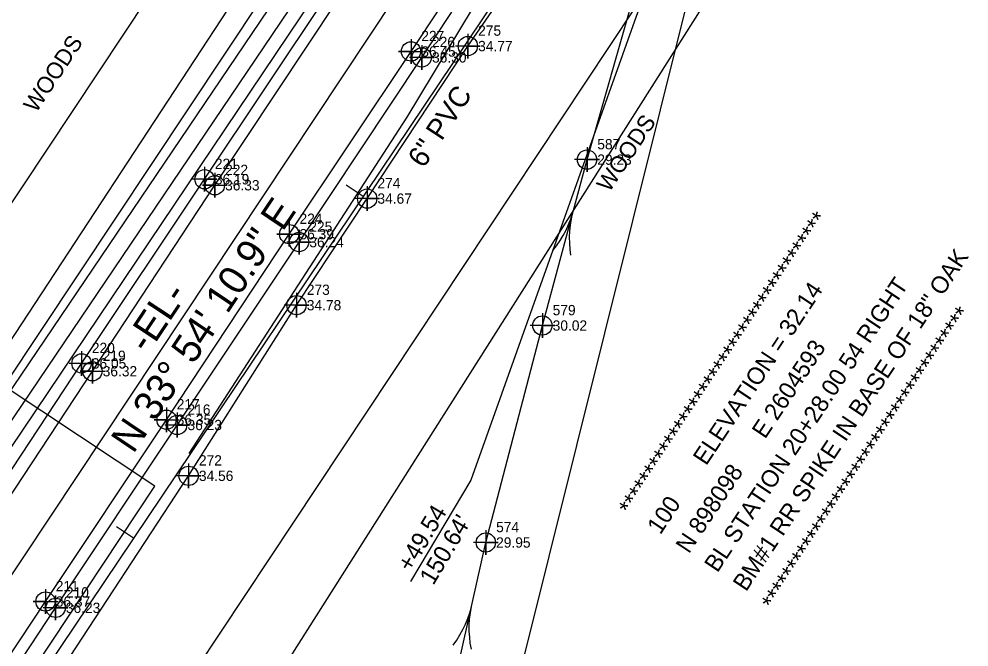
# Model space of a CAD drawing. Extents: x 2603627 to 2605187, y 896619 to 899063.
# Drawn here: x 2604393.2 to 2604624, y 897913.7 to 898066.2 of the extents above; entities that cross this region are included whole.
import ezdxf

# ---------------------------------------------------------------- set-up
doc = ezdxf.new("R2010")
doc.units = 0
for name, color, linetype in [('CTL Sheet Text', 7, 'Continuous'), ('Exist DTM Drainline Cogo Elevation', 7, 'Continuous'), ('Exist DTM Drainline Cogo Number', 7, 'Continuous'), ('Exist DTM Drainline Cogo Point CELL', 7, 'Continuous'), ('Exist Guardrail', 7, 'Continuous'), ('Exist Horizontal Alignment', 7, 'Continuous'), ('Exist Horizontal Alignment Direction Label', 7, 'Continuous'), ('Exist Horizontal Baseline Alignment', 7, 'Continuous'), ('Exist Horizontal Baseline Alignment Direction Label', 7, 'Continuous'), ('Exist Horizontal Baseline Alignment Tick small', 7, 'Continuous'), ('Exist Hydro Stream Flow Arrow CELL', 7, 'Continuous'), ('Exist Hydro Stream or Body of Water', 7, 'Continuous'), ('Exist Property Line', 7, 'Continuous'), ('Exist Property Tie Line Leader', 7, 'Continuous'), ('Exist Property Tie Line Text', 7, 'Continuous'), ('Exist Right of Way Line', 7, 'Continuous'), ('Exist Roads EOP', 7, 'Continuous'), ('Exist Roads EOP Cogo Elevation', 7, 'Continuous'), ('Exist Roads EOP Cogo Number', 7, 'Continuous'), ('Exist Roads EOP Cogo Point CELL', 7, 'Continuous'), ('Exist Roads EOT', 7, 'Continuous'), ('Exist Roads EOT Cogo Elevation', 7, 'Continuous'), ('Exist Roads EOT Cogo Number', 7, 'Continuous'), ('Exist Roads EOT Cogo Point CELL', 7, 'Continuous'), ('Exist Utilities Telephone UG Cable SUE LOS C', 7, 'Continuous'), ('Exist Utilities Telephone UG FO SUE LOS C', 7, 'Continuous'), ('Exist Utilities Water UG Line SUE LOS B', 7, 'Continuous'), ('Exist Utilities Water UG Line SUE LOS B Cogo Elevation', 7, 'Continuous'), ('Exist Utilities Water UG Line SUE LOS B Cogo Number', 7, 'Continuous'), ('Exist Utilities Water UG Line SUE LOS B Cogo Point CELL', 7, 'Continuous'), ('Exist Utilities Water UG Line SUE LOS B Text', 7, 'Continuous'), ('Exist Vegetation Woods Line', 7, 'Continuous'), ('Exist Vegetation Woods Line Text', 7, 'Continuous')]:
    doc.layers.add(name, color=color, linetype=linetype)

# ---------------------------------------------------------------- blocks, each defined once
blk = doc.blocks.new('EXIST ROADS EOP COGO POINT')
at = {"layer": 'Exist Roads EOP Cogo Point CELL'}
blk.add_lwpolyline([(0, 0.06), (0, -0.06), (0, 0), (0.06, 0), (-0.06, 0)], dxfattribs=at)
blk.add_circle((0, 0), 0.0469, dxfattribs=at)
blk = doc.blocks.new('EXIST ROADS EOT COGO POINT')
at = {"layer": 'Exist Roads EOT Cogo Point CELL'}
blk.add_lwpolyline([(0, 0.06), (0, -0.06), (0, 0), (-0.06, 0), (0.06, 0)], dxfattribs=at)
blk.add_circle((0, 0), 0.0469, dxfattribs=at)
blk = doc.blocks.new('EXIST UTILITIES WATER UG LINE SUE LOS B COGO POINT')
at = {"layer": 'Exist Utilities Water UG Line SUE LOS B Cogo Point CELL'}
blk.add_lwpolyline([(0, 0.06), (0, -0.06), (0, 0), (0.06, 0), (-0.06, 0)], dxfattribs=at)
blk.add_circle((0, 0), 0.0469, dxfattribs=at)
blk = doc.blocks.new('EXIST DTM DRAINLINE COGO POINT')
at = {"layer": 'Exist DTM Drainline Cogo Point CELL'}
blk.add_lwpolyline([(0, 0.06), (0, -0.06), (0, 0), (0.06, 0), (-0.06, 0)], dxfattribs=at)
blk.add_circle((0, 0), 0.0469, dxfattribs=at)

msp = doc.modelspace()

# ---------------------------------------------------------------- linework, layer by layer
at = {"layer": 'Exist Guardrail'}
msp.add_lwpolyline([(2604516.08, 898089.95), (2604487.4, 898042.34), (2604434.45, 897960.66)], dxfattribs=at)
at = {"layer": 'Exist Horizontal Alignment'}
msp.add_line((2604046.33, 897411.6), (2604501.12, 898096.36), dxfattribs=at)
at = {"layer": 'Exist Horizontal Baseline Alignment'}
msp.add_line((2604301.74, 897762.53), (2604544.96, 898124.44), dxfattribs=at)
at = {"layer": 'Exist Horizontal Baseline Alignment Tick small'}
for p, q in [((2604476.83, 898023.06), (2604472.68, 898025.85)), ((2604421.06, 897940.07), (2604416.91, 897942.85))]:
    msp.add_line(p, q, dxfattribs=at)
at = {"layer": 'Exist Hydro Stream Flow Arrow CELL'}
for p, q in [((2604526.4, 898014.23), (2604526.4, 898014.23)), ((2604502.01, 897918.51), (2604502.01, 897918.51))]:
    msp.add_line(p, q, dxfattribs=at)
for points in [[(2604522.9, 898009.99), (2604523.82, 898011.13), (2604524.64, 898012.39), (2604525.43, 898013.64), (2604526.1, 898014.92), (2604526.71, 898016.27), (2604527.25, 898017.66), (2604527.7, 898019.06)], [(2604527.31, 898008.81), (2604527.08, 898010.25), (2604527.01, 898011.75), (2604526.95, 898013.23), (2604527.02, 898014.67), (2604527.17, 898016.15), (2604527.4, 898017.62), (2604527.7, 898019.06)], [(2604498.68, 897914.14), (2604499.56, 897915.31), (2604500.32, 897916.6), (2604501.06, 897917.88), (2604501.68, 897919.19), (2604502.23, 897920.57), (2604502.71, 897921.98), (2604503.11, 897923.39)], [(2604503.15, 897913.13), (2604502.85, 897914.57), (2604502.72, 897916.06), (2604502.6, 897917.54), (2604502.6, 897918.98), (2604502.69, 897920.46), (2604502.86, 897921.95), (2604503.11, 897923.39)]]:
    msp.add_lwpolyline(points, dxfattribs=at)
at = {"layer": 'Exist Hydro Stream or Body of Water'}
msp.add_lwpolyline([(2604496.63, 897894.57), (2604506.62, 897939.05), (2604520.36, 897991.75), (2604531.2, 898032.05), (2604542.79, 898072.73), (2604553.75, 898102.57), (2604562.26, 898124.95)], dxfattribs=at)
at = {"layer": 'Exist Property Line'}
msp.add_line((2604562.45, 898098.35), (2604410.23, 897487.88), dxfattribs=at)
at = {"layer": 'Exist Property Tie Line Leader'}
msp.add_lwpolyline([(2604573.79, 898143.82), (2604569.62, 898141.11), (2604502.96, 897954.22), (2604488.28, 897929.59)], dxfattribs=at)
at = {"layer": 'Exist Right of Way Line'}
for p, q in [((2604004.68, 897439.26), (2604459.47, 898124.02)), ((2604087.98, 897383.94), (2604542.77, 898068.69))]:
    msp.add_line(p, q, dxfattribs=at)
at = {"layer": 'Exist Roads EOP'}
for points in [[(2604034.94, 897419.16), (2604054.97, 897449.51), (2604085.58, 897495.18), (2604114.88, 897539.87), (2604143.93, 897583.57), (2604172.72, 897627.19), (2604201.64, 897670.62), (2604230.5, 897714.45), (2604261.1, 897760.21), (2604291.23, 897805.76), (2604320.82, 897850.24), (2604350.34, 897894.81), (2604379.01, 897938.02), (2604408.4, 897982.56), (2604438.29, 898027.28), (2604468.22, 898072.28), (2604496.92, 898115.7)], [(2604057.72, 897404.05), (2604078.22, 897434.83), (2604108.36, 897480.05), (2604137.93, 897524.86), (2604167.35, 897568.96), (2604196.06, 897612.17), (2604224.86, 897655.68), (2604253.51, 897698.95), (2604283.96, 897744.64), (2604314.74, 897791.03), (2604343.97, 897835.34), (2604373.31, 897879.6), (2604402.1, 897923.18), (2604431.64, 897967.59), (2604461.24, 898012.02), (2604491.05, 898056.88), (2604519.7, 898100.47)]]:
    msp.add_lwpolyline(points, dxfattribs=at)
at = {"layer": 'Exist Roads EOT'}
for points in [[(2604037.37, 897417.54), (2604057.46, 897447.93), (2604087.91, 897493.66), (2604117.35, 897538.28), (2604146.54, 897581.98), (2604175.28, 897625.51), (2604204.1, 897668.97), (2604233.05, 897712.63), (2604263.81, 897758.51), (2604293.89, 897804.07), (2604323.3, 897848.54), (2604352.86, 897893.08), (2604381.65, 897936.11), (2604411.04, 897980.65), (2604440.78, 898025.82), (2604470.61, 898070.74), (2604499.36, 898114.11)], [(2604055.13, 897405.77), (2604075.39, 897436.3), (2604105.72, 897481.84), (2604135.41, 897526.58), (2604164.51, 897570.47), (2604193.14, 897613.84), (2604222.02, 897657.58), (2604250.73, 897700.63), (2604281.08, 897746.07), (2604311.9, 897792.56), (2604341.37, 897836.94), (2604370.82, 897881.24), (2604399.64, 897924.71), (2604429.03, 897968.88), (2604458.85, 898013.95), (2604488.44, 898058.33), (2604517.14, 898101.52)]]:
    msp.add_lwpolyline(points, dxfattribs=at)
at = {"layer": 'Exist Utilities Telephone UG Cable SUE LOS C'}
for p, q in [((2604364.02, 897921.59), (2604492.57, 898112.76)), ((2604389.62, 897977.06), (2604474.1, 898104.18)), ((2604426.24, 897952.72), (2604389.62, 897977.06)), ((2604201.56, 897614.6), (2604426.24, 897952.72))]:
    msp.add_line(p, q, dxfattribs=at)
at = {"layer": 'Exist Utilities Telephone UG FO SUE LOS C'}
for p, q in [((2604020.98, 897428.41), (2604461.82, 898080.46)), ((2604024.53, 897426.06), (2604465.37, 898078.1))]:
    msp.add_line(p, q, dxfattribs=at)
at = {"layer": 'Exist Utilities Water UG Line SUE LOS B'}
msp.add_lwpolyline([(2604076.5, 897391.6), (2604089.19, 897412.44), (2604108.02, 897444.81), (2604130.46, 897486.17), (2604138.61, 897502.5), (2604141.74, 897510.42), (2604157.29, 897542.11), (2604195.61, 897598.86), (2604232.99, 897655.2), (2604269.72, 897709.19), (2604303.43, 897758.71), (2604343.24, 897819.02), (2604371.6, 897861.28), (2604402.52, 897906.63), (2604434.42, 897955.25), (2604460.63, 897996.69), (2604477.79, 898022.59), (2604502.25, 898059.64), (2604529.4, 898098.89), (2604530.47, 898100.43), (2604537.02, 898109.88), (2604550.55, 898129.28)], dxfattribs=at)
at = {"layer": 'Exist Vegetation Woods Line'}
for points in [[(2604476.15, 898117.83), (2604185.5, 897674.67)], [(2604278.2, 897626.01), (2604559.06, 898068.86)]]:
    msp.add_lwpolyline(points, dxfattribs=at)

# ---------------------------------------------------------------- block references
at = {"layer": 'Exist DTM Drainline Cogo Point CELL', "xscale": 50, "yscale": 50}
for p in [(2604531.2, 898032.05), (2604520.36, 897991.75), (2604506.62, 897939.05)]:
    msp.add_blockref('EXIST DTM DRAINLINE COGO POINT', p, dxfattribs=at)
at = {"layer": 'Exist Roads EOP Cogo Point CELL', "xscale": 50, "yscale": 50}
for p in [(2604491.05, 898056.88), (2604438.29, 898027.28), (2604461.24, 898012.02), (2604408.4, 897982.56), (2604431.64, 897967.59), (2604402.1, 897923.18)]:
    msp.add_blockref('EXIST ROADS EOP COGO POINT', p, dxfattribs=at)
at = {"layer": 'Exist Roads EOT Cogo Point CELL', "xscale": 50, "yscale": 50}
for p in [(2604488.44, 898058.33), (2604440.78, 898025.82), (2604458.85, 898013.95), (2604411.04, 897980.65), (2604429.03, 897968.88), (2604399.64, 897924.71)]:
    msp.add_blockref('EXIST ROADS EOT COGO POINT', p, dxfattribs=at)
at = {"layer": 'Exist Utilities Water UG Line SUE LOS B Cogo Point CELL', "xscale": 50, "yscale": 50}
for p in [(2604502.25, 898059.64), (2604477.79, 898022.59), (2604460.63, 897996.69), (2604434.42, 897955.25)]:
    msp.add_blockref('EXIST UTILITIES WATER UG LINE SUE LOS B COGO POINT', p, dxfattribs=at)

# ---------------------------------------------------------------- texts
at = {"layer": 'CTL Sheet Text'}
for s, p in [('****************************************', (2604542.07, 897945.37)), ('BM#1 RR SPIKE IN BASE OF 18" OAK', (2604569.84, 897926.93)), ('BL STATION 20+28.00 54 RIGHT', (2604562.89, 897931.54)), ('100       ELEVATION = 32.14', (2604549.01, 897940.76)), ('****************************************', (2604576.78, 897922.32)), ('N 898098      E 2604593', (2604555.95, 897936.15))]:
    msp.add_text(s, height=4.1667, rotation=56.4094, dxfattribs=at).set_placement(p)
at = {"layer": 'Exist DTM Drainline Cogo Elevation'}
for s, p in [('29.23', (2604533.7, 898030.8)), ('30.02', (2604522.86, 897990.5)), ('29.95', (2604509.12, 897937.8))]:
    msp.add_text(s, height=2.5, dxfattribs=at).set_placement(p)
at = {"layer": 'Exist DTM Drainline Cogo Number'}
for s, p in [('587', (2604533.7, 898034.55)), ('579', (2604522.86, 897994.25)), ('574', (2604509.12, 897941.55))]:
    msp.add_text(s, height=2.5, dxfattribs=at).set_placement(p)
at = {"layer": 'Exist Horizontal Alignment Direction Label'}
msp.add_text('-EL-', height=7, rotation=56.4094, dxfattribs=at).set_placement((2604424.55, 897984.67))
at = {"layer": 'Exist Horizontal Baseline Alignment Direction Label'}
msp.add_text('N 33%%d 54\' 10.9" E', height=7, rotation=56.097, dxfattribs=at).set_placement((2604420.97, 897960.41))
at = {"layer": 'Exist Property Tie Line Text'}
for s, p in [('+49.54', (2604488.41, 897931.64)), ("150.64'", (2604493.86, 897928.47))]:
    msp.add_text(s, height=4.2, rotation=59.1717, dxfattribs=at).set_placement(p)
at = {"layer": 'Exist Roads EOP Cogo Elevation'}
for s, p in [('36.30', (2604493.55, 898055.63)), ('36.19', (2604440.79, 898026.03)), ('36.24', (2604463.74, 898010.77)), ('36.05', (2604410.9, 897981.31)), ('36.23', (2604434.14, 897966.34)), ('36.23', (2604404.6, 897921.93))]:
    msp.add_text(s, height=2.5, dxfattribs=at).set_placement(p)
at = {"layer": 'Exist Roads EOP Cogo Number'}
for s, p in [('226', (2604493.55, 898059.38)), ('221', (2604440.79, 898029.78)), ('225', (2604463.74, 898014.52)), ('220', (2604410.9, 897985.06)), ('216', (2604434.14, 897970.09)), ('210', (2604404.6, 897925.68))]:
    msp.add_text(s, height=2.5, dxfattribs=at).set_placement(p)
at = {"layer": 'Exist Roads EOT Cogo Elevation'}
for s, p in [('36.45', (2604490.94, 898057.08)), ('36.33', (2604443.28, 898024.57)), ('36.39', (2604461.35, 898012.7)), ('36.32', (2604413.54, 897979.4)), ('36.35', (2604431.53, 897967.63)), ('36.37', (2604402.14, 897923.46))]:
    msp.add_text(s, height=2.5, dxfattribs=at).set_placement(p)
at = {"layer": 'Exist Roads EOT Cogo Number'}
for s, p in [('227', (2604490.94, 898060.83)), ('222', (2604443.28, 898028.32)), ('224', (2604461.35, 898016.45)), ('219', (2604413.54, 897983.15)), ('217', (2604431.53, 897971.38)), ('211', (2604402.14, 897927.21))]:
    msp.add_text(s, height=2.5, dxfattribs=at).set_placement(p)
at = {"layer": 'Exist Utilities Water UG Line SUE LOS B Cogo Elevation'}
for s, p in [('34.77', (2604504.75, 898058.39)), ('34.67', (2604480.29, 898021.34)), ('34.78', (2604463.13, 897995.44)), ('34.56', (2604436.92, 897954))]:
    msp.add_text(s, height=2.5, dxfattribs=at).set_placement(p)
at = {"layer": 'Exist Utilities Water UG Line SUE LOS B Cogo Number'}
for s, p in [('275', (2604504.75, 898062.14)), ('274', (2604480.29, 898025.09)), ('273', (2604463.13, 897999.19)), ('272', (2604436.92, 897957.75))]:
    msp.add_text(s, height=2.5, dxfattribs=at).set_placement(p)
at = {"layer": 'Exist Utilities Water UG Line SUE LOS B Text'}
msp.add_text('6" PVC', height=5, rotation=56.5594, dxfattribs=at).set_placement((2604491.51, 898029.77))
at = {"layer": 'Exist Vegetation Woods Line Text'}
for p in [(2604397.38, 898043.22), (2604536.6, 898023.91)]:
    msp.add_text('WOODS', height=4, rotation=56.4094, dxfattribs=at).set_placement(p)

doc.saveas('drawing.dxf')
